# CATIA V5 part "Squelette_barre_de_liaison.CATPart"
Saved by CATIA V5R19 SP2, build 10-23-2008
Part number: squelette_barre_de_liaison
Bounding box of the stored display mesh (mm): x -10 to -10, y -294 to 0, z -96 to -96
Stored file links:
  G:\EU_thinkMotion\CFAO_2010\MMS_groupe3\MMS_groupe3\pmayet\pmayet_assemblage_animation\pmayet_assemblage_animation\Squelette_barre_de_liaison.CATPart
  G:\EU_thinkMotion\CFAO_2010\MMS_groupe3\MMS_groupe3\pmayet\pmayet_assemblage_animation\pmayet_assemblage_animation\pmayet_assemblage_animation.CATProduct
  G:\EU_thinkMotion\CFAO_2010\MMS_groupe3\MMS_groupe3\pmayet\pmayet_assemblage_animation\pmayet_assemblage_animation\Squelette_de_base.CATPart
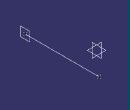
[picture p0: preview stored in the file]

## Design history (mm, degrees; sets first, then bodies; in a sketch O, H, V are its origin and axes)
Set1
  Point1 "Point.22_barre_liaison": linked copy from another document
  Point2 "Point.23_barre_liaison_2": linked copy from another document
Set2
  Line1: type PtPt, FirstPoint Point1, SecondPoint Point2
  Plane1: type OffsetPt, RefPlane yz-plane, RefPoint Point1
Body1 (main body)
